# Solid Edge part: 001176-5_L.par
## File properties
Last saved by: morva
Revision: 82
Accuracy: 0.990
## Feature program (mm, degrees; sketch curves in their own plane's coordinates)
body "unnamed Body 1"
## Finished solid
Body 1: solid body, 44 faces, 88 edges, 47 vertices.
  Faces by surface: cylinder 18, plane 14, spline 4, cone 2, spun 2, swept 2, torus 2
  Edges by curve: curve on surface 32, line 31, circle 23, spline 2
Bounding box of the edges (mm; curved faces can reach further): 12.552 x 7.036 x 19.252, from (509.3027, 416.4835, -88.4398) to (521.8543, 423.5198, -69.1881).
Cylindrical faces by radius (mm): R0.4 x5, R0.4491 x2, R0.4493 x4, R0.4507 x2, R2 x2, R3.5 x3
Conical faces (half-angle, radius in mm at the cone's reference point): 45 deg R2 x2
Toroidal faces (ring radius, tube radius in mm): R2 r1.5 x2
Planar faces by outward normal: oblique 14
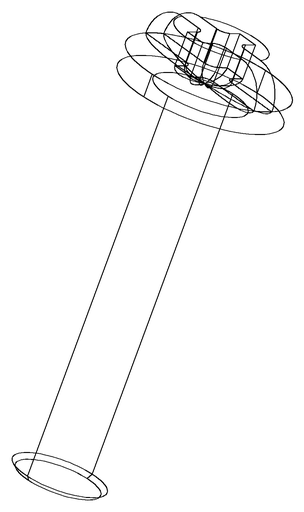
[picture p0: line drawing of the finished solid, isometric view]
